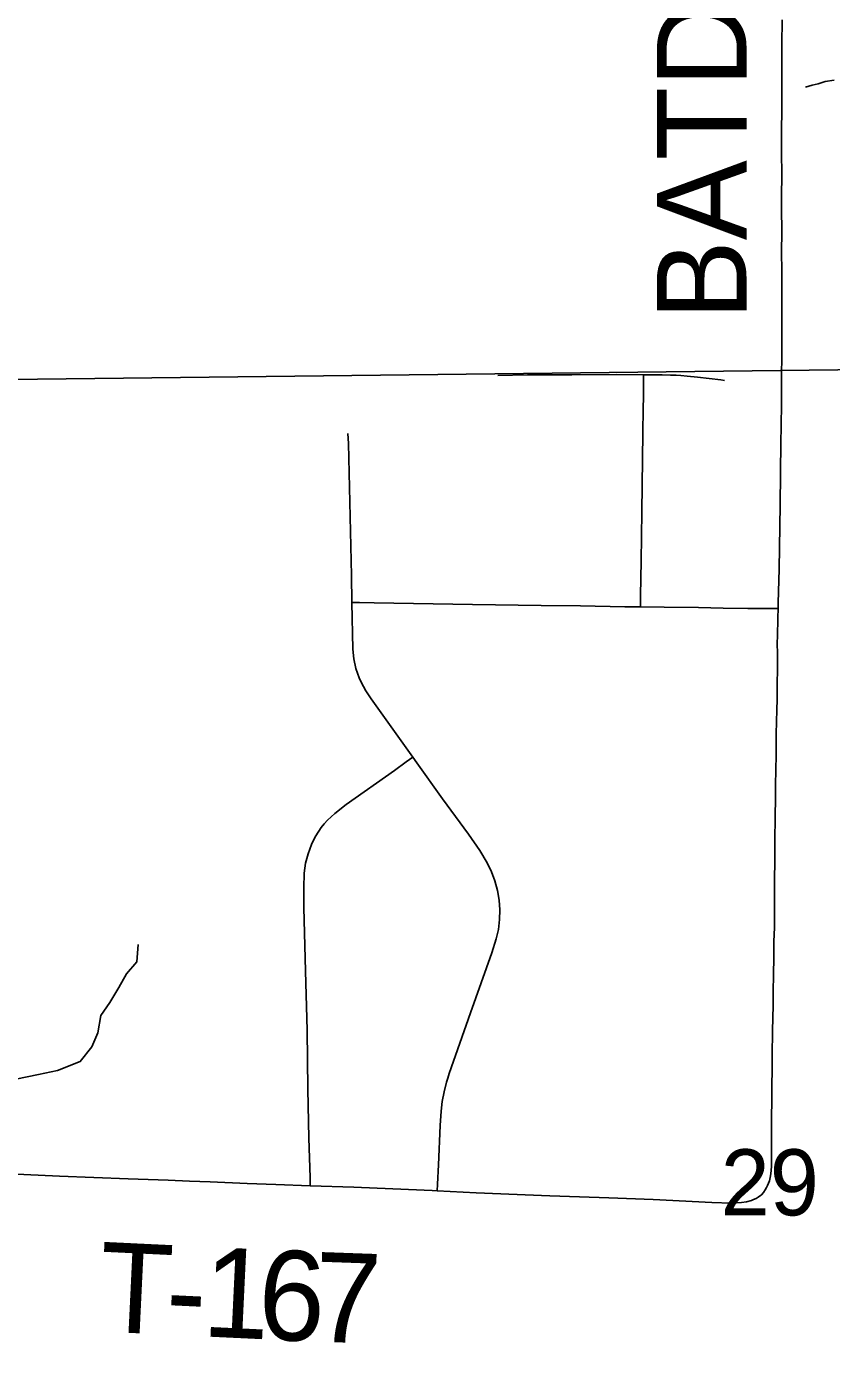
# Model space of a CAD drawing. Extents: x 0 to 34, y 0 to 22.
# Drawn here: x 6.953 to 7.463, y 16.614 to 17.466 of the extents above; entities that cross this region are included whole.
import ezdxf

# ---------------------------------------------------------------- set-up
doc = ezdxf.new("R2010")
doc.units = 0
for name, color, linetype in [('GM_X_Major_River_Text', 7, 'Continuous'), ('GM_X_Minor_River', 7, 'Continuous'), ('GM_X_Section', 7, 'Continuous'), ('GM_X_Section_Text', 7, 'Continuous'), ('GM_X_Township_Road', 7, 'Continuous'), ('GM_X_Township_Road_Text', 7, 'Continuous')]:
    doc.layers.add(name, color=color, linetype=linetype)

msp = doc.modelspace()

# ---------------------------------------------------------------- linework, layer by layer
at = {"layer": 'GM_X_Minor_River'}
for points in [[(7.46501, 17.43281), (7.45931, 17.43197), (7.45477, 17.43039), (7.45098, 17.42958), (7.44681, 17.42838)], [(6.94638, 16.79948), (6.96076, 16.80245), (6.97288, 16.80505), (6.98727, 16.81067), (6.99449, 16.82012), (6.9983, 16.82883), (7.00023, 16.83982), (7.00594, 16.84814), (7.01165, 16.8576), (7.0166, 16.8663), (7.02305, 16.87386), (7.02385, 16.88486)]]:
    msp.add_lwpolyline(points, dxfattribs=at)
at = {"layer": 'GM_X_Section'}
for points in [[(7.92171, 18.27008), (7.92008, 17.25434), (6.92373, 17.24282), (6.91054, 18.26226)], [(6.92373, 17.24282), (7.92008, 17.25434), (7.92004, 16.95796), (7.93409, 16.26707), (7.50296, 16.23822), (6.93034, 16.22819)]]:
    msp.add_lwpolyline(points, close=True, dxfattribs=at)
at = {"layer": 'GM_X_Township_Road'}
for points in [[(7.4295, 17.09791), (7.42958, 17.1012), (7.43017, 17.12293), (7.43084, 17.16325), (7.43127, 17.20354), (7.43145, 17.21288), (7.43154, 17.22842), (7.4316, 17.24393), (7.43167, 17.2501), (7.43179, 17.25304), (7.43183, 17.25866), (7.43186, 17.26833), (7.43189, 17.27573), (7.43191, 17.28297), (7.43191, 17.28823), (7.43191, 17.29234), (7.43192, 17.29773), (7.43189, 17.30073), (7.43184, 17.31312), (7.43172, 17.32242), (7.43178, 17.33793), (7.43168, 17.35039), (7.43158, 17.35964), (7.43177, 17.37209), (7.43163, 17.38764), (7.43153, 17.39012), (7.43166, 17.39324), (7.43187, 17.42122), (7.4319, 17.45541), (7.43196, 17.47096)], [(7.25194, 17.24555), (7.27067, 17.24595), (7.29876, 17.24591), (7.32685, 17.24619), (7.34423, 17.2459)], [(7.3422, 17.09887), (7.34231, 17.10606), (7.34263, 17.12794), (7.34316, 17.15922), (7.34366, 17.20927), (7.344, 17.22442), (7.34411, 17.23212), (7.34419, 17.23783), (7.34423, 17.2459)], [(7.34423, 17.2459), (7.35608, 17.24596), (7.36119, 17.24581), (7.36489, 17.2457), (7.36777, 17.24549), (7.37185, 17.24519), (7.37849, 17.24457), (7.39328, 17.24271), (7.39541, 17.24231)], [(7.15937, 17.10161), (7.15904, 17.1187), (7.15811, 17.16526), (7.15759, 17.18387), (7.15721, 17.20249), (7.15687, 17.2087)], [(7.15937, 17.10161), (7.16412, 17.10159), (7.17346, 17.10153), (7.23573, 17.10032), (7.27937, 17.09973), (7.3043, 17.09951), (7.33235, 17.09895), (7.3422, 17.09887)], [(7.19799, 17.00363), (7.1842, 17.02279), (7.17157, 17.04049), (7.16823, 17.04573), (7.16526, 17.05119), (7.16396, 17.05401), (7.16284, 17.05691), (7.16194, 17.05988), (7.16064, 17.06595), (7.15993, 17.07212), (7.15937, 17.10161)], [(7.3422, 17.09887), (7.3573, 17.09874), (7.37913, 17.09843), (7.39472, 17.09815), (7.41027, 17.09787), (7.41957, 17.09786), (7.42607, 17.09789), (7.4295, 17.09791)], [(7.41886, 16.72613), (7.42028, 16.72777), (7.42136, 16.72934), (7.42216, 16.73091), (7.42282, 16.73209), (7.42393, 16.73509), (7.42464, 16.73819), (7.42504, 16.74134), (7.42524, 16.7445), (7.42525, 16.7508), (7.42526, 16.76232), (7.42527, 16.76808), (7.42528, 16.77566), (7.42541, 16.78552), (7.42554, 16.79455), (7.42564, 16.8064), (7.4257, 16.81445), (7.42599, 16.83024), (7.42628, 16.84644), (7.42634, 16.85573), (7.42658, 16.865), (7.42668, 16.87742), (7.42674, 16.88672), (7.42713, 16.89569), (7.42719, 16.9003), (7.42725, 16.90431), (7.42724, 16.91634), (7.4273, 16.94738), (7.4274, 16.95044), (7.42759, 16.96594), (7.42774, 16.97758), (7.42783, 16.98452), (7.4281, 16.99683), (7.42815, 17.00357), (7.42821, 17.01097), (7.42827, 17.01788), (7.42852, 17.02675), (7.4287, 17.033), (7.42893, 17.0409), (7.42899, 17.06869), (7.42892, 17.07625), (7.42903, 17.0802), (7.42935, 17.09193), (7.4295, 17.09791)], [(7.13302, 16.73201), (7.13286, 16.73727), (7.13213, 16.7621), (7.13154, 16.79324), (7.13096, 16.8306), (7.13007, 16.86794), (7.12902, 16.90839), (7.12889, 16.92085), (7.12918, 16.93018), (7.12949, 16.93328), (7.13001, 16.93634), (7.13167, 16.94234), (7.1338, 16.94819), (7.1351, 16.95101), (7.13656, 16.95375), (7.13997, 16.95895), (7.14188, 16.9614), (7.14395, 16.96372), (7.14848, 16.96796), (7.15583, 16.97367), (7.18632, 16.99507), (7.19384, 17.00059), (7.19799, 17.00363)], [(7.21351, 16.72874), (7.21373, 16.73297), (7.21434, 16.7453), (7.21524, 16.77006), (7.21592, 16.77933), (7.21666, 16.78547), (7.2178, 16.79156), (7.21942, 16.79768), (7.22018, 16.80016), (7.22107, 16.80309), (7.23455, 16.84153), (7.24808, 16.87951), (7.25082, 16.88841), (7.25219, 16.89446), (7.25292, 16.90063), (7.25306, 16.90683), (7.25264, 16.91303), (7.25161, 16.91916), (7.25001, 16.92515), (7.24784, 16.93097), (7.24515, 16.93657), (7.24037, 16.94455), (7.23326, 16.95474), (7.21669, 16.97726), (7.20054, 17.00009), (7.19799, 17.00363)], [(6.9287, 16.74018), (6.9741, 16.73815), (7.01761, 16.73645), (7.04285, 16.73542), (7.0565, 16.73488), (7.06964, 16.73437), (7.09301, 16.7335), (7.11125, 16.73282), (7.13302, 16.73201)], [(7.13302, 16.73201), (7.16052, 16.73098), (7.18537, 16.72995), (7.21023, 16.72889), (7.21351, 16.72874)], [(7.21351, 16.72874), (7.23821, 16.72757), (7.28488, 16.7256), (7.30356, 16.72499), (7.32222, 16.72432), (7.3502, 16.72324), (7.38747, 16.72137), (7.40001, 16.72099), (7.40629, 16.7213), (7.40944, 16.72181), (7.41253, 16.72272), (7.41399, 16.72325), (7.41551, 16.72399), (7.41694, 16.72482), (7.41886, 16.72613)]]:
    msp.add_lwpolyline(points, dxfattribs=at)

# ---------------------------------------------------------------- texts
at = {"layer": 'GM_X_Major_River_Text'}
msp.add_text('Creek', height=0.094723, rotation=60.7664, dxfattribs=at).set_placement((7.48435, 16.34727))
at = {"layer": 'GM_X_Section_Text'}
msp.add_text('29', height=0.041856, rotation=0.00001, dxfattribs=at).set_placement((7.39307, 16.71319))
at = {"layer": 'GM_X_Township_Road_Text'}
for s, height, rotation, p in [('BATDORF', 0.056818, 90, (7.40946, 17.28062)), ('T', 0.05682, 357.24974, (6.99816, 16.6397)), ('1', 0.05682, 357.29438, (7.06396, 16.63654)), ('6', 0.05682, 357.42425, (7.09906, 16.63489)), ('7', 0.05682, 357.96921, (7.13462, 16.63329)), ('-', 0.05682, 357.25649, (7.04062, 16.63766))]:
    msp.add_text(s, height=height, rotation=rotation, dxfattribs=at).set_placement(p)

doc.saveas('drawing.dxf')
